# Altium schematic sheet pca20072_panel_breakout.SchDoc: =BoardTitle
size A4; Organization: Nordic Semiconductor; DocumentNumber: 4; SheetNumber: 4; SheetTotal: 6; CompanyName: Nordic Semiconductor; DocumentSize: A4
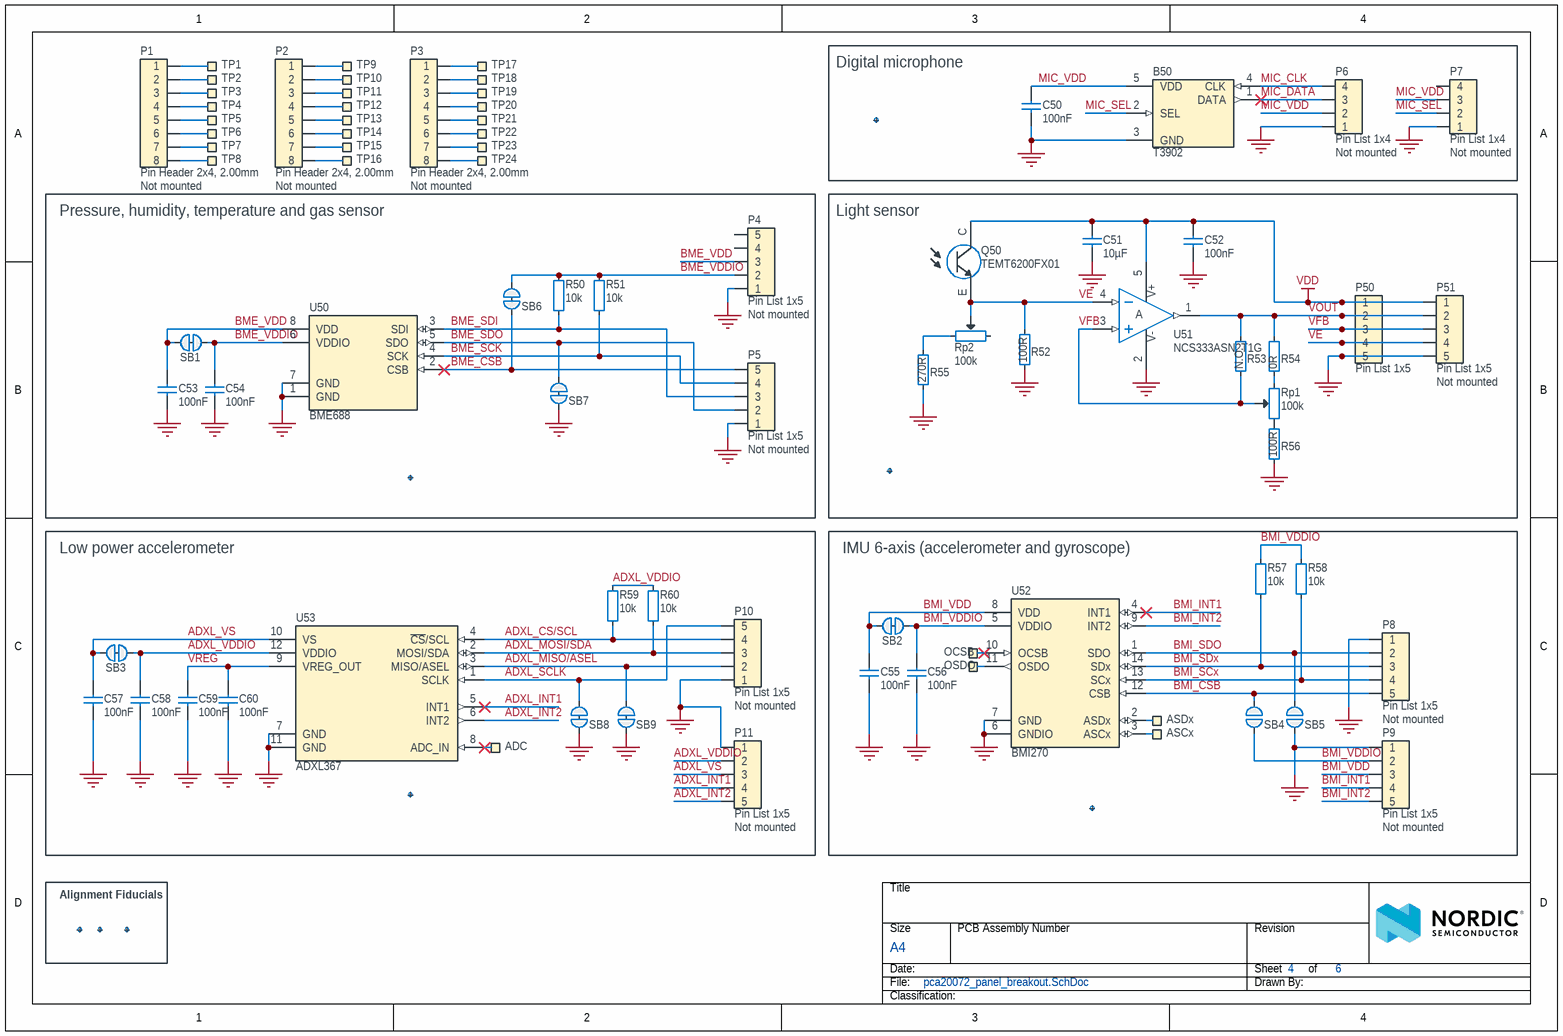
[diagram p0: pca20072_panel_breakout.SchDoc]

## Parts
ADC  Ø1.2mm,SMD  [TP_SMD_D1.2mm]  (value not drawn)  (no BOM)
ASCx  Ø1.2mm,SMD  [TP_SMD_D1.2mm]  (value not drawn)  (no BOM)
ASDx  Ø1.2mm,SMD  [TP_SMD_D1.2mm]  (value not drawn)  (no BOM)
B50  T3902  [T3902]
C50  100nF  [CAPC0603X03L_C]
C51  10µF  [CAPC1005X04L_C2]
C52  100nF  [CAPC0603X03L_C]
C53  100nF  [CAPC0603X03L_C]
C54  100nF  [CAPC0603X03L_C]
C55  100nF  [CAPC0603X03L_C]
C56  100nF  [CAPC0603X03L_C]
C57  100nF  [CAPC0603X03L_C]
C58  100nF  [CAPC0603X03L_C]
C59  100nF  [CAPC0603X03L_C]
C60  100nF  [CAPC0603X03L_C]
Fid50  Fiducial mark  [Fiducial]  (value not drawn)
Fid51  Fiducial mark  [Fiducial]  (value not drawn)
Fid52  Fiducial mark  [Fiducial]  (value not drawn)
Fid53  Fiducial mark  [Fiducial]  (value not drawn)
Fid54  Fiducial mark  [Fiducial]  (value not drawn)
Fid55  Fiducial mark  [Fiducial]  (value not drawn)
Fid56  Fiducial mark  [Fiducial]  (value not drawn)
Fid57  Fiducial mark  [Fiducial]  (value not drawn)
OCSB  Ø1.2mm,SMD  [TP_SMD_D1.2mm]  (value not drawn)  (no BOM)
OSDO  Ø1.2mm,SMD  [TP_SMD_D1.2mm]  (value not drawn)  (no BOM)
P1  Pin Header 2x4, 2.00mm  Assembly: Not mounted  [HDR_2x4_TH_2.00MM-NC]
P2  Pin Header 2x4, 2.00mm  Assembly: Not mounted  [HDR_2x4_TH_2.00MM-NC]
P3  Pin Header 2x4, 2.00mm  Assembly: Not mounted  [HDR_2x4_TH_2.00MM-NC]
P4  Pin List 1x5  Assembly: Not mounted  [LIST_1x5-NC]
P5  Pin List 1x5  Assembly: Not mounted  [LIST_1x5-NC]
P6  Pin List 1x4  Assembly: Not mounted  [LIST_1x4-NC]
P7  Pin List 1x4  Assembly: Not mounted  [LIST_1x4-NC]
P8  Pin List 1x5  Assembly: Not mounted  [LIST_1x5-NC]
P9  Pin List 1x5  Assembly: Not mounted  [LIST_1x5-NC]
P10  Pin List 1x5  Assembly: Not mounted  [LIST_1x5-NC]
P11  Pin List 1x5  Assembly: Not mounted  [LIST_1x5-NC]
P50  Pin List 1x5  [LIST_1x5_SMD]
P51  Pin List 1x5  Assembly: Not mounted  [LIST_1x5-NC]
Q50  TEMT6200FX01  [TEMT6200FX01]
R50  10k  [RESC1005X04L]
R51  10k  [RESC1005X04L]
R52  100R  [RESC1005X04L]
R53  N.C.  [RESC1005X04L_NC]
R54  0R  [RESC1005X04L]
R55  270R  [RESC1005X04L]
R56  100R  [RESC1005X04L]
R57  10k  [RESC1005X04L]
R58  10k  [RESC1005X04L]
R59  10k  [RESC1005X04L]
R60  10k  [RESC1005X04L]
Rp1  100k  [POT.TRIM_23B]
Rp2  100k  [POT.TRIM_23B]
SB1  Solderbridge  [Solderbridge_Shorted]  (value not drawn)  (net tie, no BOM)
SB2  Solderbridge  [Solderbridge_Shorted]  (value not drawn)  (net tie, no BOM)
SB3  Solderbridge  [Solderbridge_Shorted]  (value not drawn)  (net tie, no BOM)
SB4  Solderbridge  [Solderbridge]  (value not drawn)  (no BOM)
SB5  Solderbridge  [Solderbridge]  (value not drawn)  (no BOM)
SB6  Solderbridge  [Solderbridge_Shorted]  (value not drawn)  (net tie, no BOM)
SB7  Solderbridge  [Solderbridge_Shorted]  (value not drawn)  (net tie, no BOM)
SB8  Solderbridge  [Solderbridge_Shorted]  (value not drawn)  (net tie, no BOM)
SB9  Solderbridge  [Solderbridge_Shorted]  (value not drawn)  (net tie, no BOM)
TP1  TP  [TESTPAD-TH]  (value not drawn)  (no BOM)
TP2  TP  [TESTPAD-TH]  (value not drawn)  (no BOM)
TP3  TP  [TESTPAD-TH]  (value not drawn)  (no BOM)
TP4  TP  [TESTPAD-TH]  (value not drawn)  (no BOM)
TP5  TP  [TESTPAD-TH]  (value not drawn)  (no BOM)
TP6  TP  [TESTPAD-TH]  (value not drawn)  (no BOM)
TP7  TP  [TESTPAD-TH]  (value not drawn)  (no BOM)
TP8  TP  [TESTPAD-TH]  (value not drawn)  (no BOM)
TP9  TP  [TESTPAD-TH]  (value not drawn)  (no BOM)
TP10  TP  [TESTPAD-TH]  (value not drawn)  (no BOM)
TP11  TP  [TESTPAD-TH]  (value not drawn)  (no BOM)
TP12  TP  [TESTPAD-TH]  (value not drawn)  (no BOM)
TP13  TP  [TESTPAD-TH]  (value not drawn)  (no BOM)
TP14  TP  [TESTPAD-TH]  (value not drawn)  (no BOM)
TP15  TP  [TESTPAD-TH]  (value not drawn)  (no BOM)
TP16  TP  [TESTPAD-TH]  (value not drawn)  (no BOM)
TP17  TP  [TESTPAD-TH]  (value not drawn)  (no BOM)
TP18  TP  [TESTPAD-TH]  (value not drawn)  (no BOM)
TP19  TP  [TESTPAD-TH]  (value not drawn)  (no BOM)
TP20  TP  [TESTPAD-TH]  (value not drawn)  (no BOM)
TP21  TP  [TESTPAD-TH]  (value not drawn)  (no BOM)
TP22  TP  [TESTPAD-TH]  (value not drawn)  (no BOM)
TP23  TP  [TESTPAD-TH]  (value not drawn)  (no BOM)
TP24  TP  [TESTPAD-TH]  (value not drawn)  (no BOM)
U50  BME688  [BME680]
U51  NCS333ASN2T1G  [SOT95P275X110-5N]
U52  BMI270  [BMI270]
U53  ADXL367  [LGA50P220X230X97-12N]

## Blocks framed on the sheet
Digital microphone: B50 C50 Fid50 P6 P7
Pressure, humidity, temperature and gas sensor: C53 C54 Fid52 P4 P5 R50 R51 SB1 SB6 SB7 U50
Light sensor: C51 C52 Fid51 P50 P51 Q50 R52-R56 Rp1 Rp2 U51
Low power accelerometer: ADC C57-C60 Fid54 P10 P11 R59 R60 SB3 SB8 SB9 U53
IMU 6-axis (accelerometer and gyroscope): ASCx ASDx C55 C56 Fid53 OCSB OSDO P8 P9 R57 R58 SB2 SB4 SB5 U52
Alignment Fiducials: Fid55-Fid57

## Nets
GND: B50.3(GND) C50.1 C51.2 C52.2 C53.1 C54.1 C55.1 C56.1 C57.1 C58.1 C59.1 C60.1 P4.1 P5.1 P6.1 P7.1 P8.1 P9.1 P10.1 P11.1 P50.5 P51.5 R52.1 R55.1 R56.1 SB5.2 SB7.2 SB8.2 SB9.2 U50.1(GND) U50.7(GND) U51.2(VSS) U52.6(GNDIO) U52.7(GND) U53.7(GND) U53.11(GND)
VDD: C51.1 C52.1 P50.1 P51.1 Q50.C U51.5(VDD)
ADXL_CS/SCL: P10.4 R59.2 U53.4(~{CS}/SCL)
ADXL_INT1: P11.4 U53.5(INT1)
ADXL_INT2: P11.5 U53.6(INT2)
ADXL_MISO/ASEL: P10.2 SB9.1 U53.3(MISO/ASEL)
ADXL_MOSI/SDA: P10.3 R60.2 U53.2(MOSI/SDA)
ADXL_SCLK: P10.5 SB8.1 U53.1(SCLK)
ADXL_VDDIO: C58.2 P11.2 R59.1 R60.1 SB3.2 U53.12(VDDIO)
ADXL_VS: C57.2 P11.3 SB3.1 U53.10(VS)
BME_CSB: P5.5 SB6.1 U50.2(CSB)
BME_SCK: P5.4 R51.2 U50.4(SCK)
BME_SDI: P5.3 R50.2 U50.3(SDI)
BME_SDO: P5.2 SB7.1 U50.5(SDO)
BME_VDD: C53.2 P4.3 SB1.2 U50.8(VDD)
BME_VDDIO: C54.2 P4.2 R50.1 R51.1 SB1.1 SB6.2 U50.6(VDDIO)
BMI_CSB: P8.5 SB4.1 U52.12(CSB)
BMI_INT1: P9.4 U52.4(INT1)
BMI_INT2: P9.5 U52.9(INT2)
BMI_SCx: P8.4 R58.2 U52.13(SCx)
BMI_SDO: P8.2 SB5.1 U52.1(SDO)
BMI_SDx: P8.3 R57.2 U52.14(SDx)
BMI_VDD: C55.2 P9.3 SB2.1 U52.8(VDD)
BMI_VDDIO: C56.2 P9.2 R57.1 R58.1 SB2.2 SB4.2 U52.5(VDDIO)
MIC_CLK: B50.4(CLK) P6.4
MIC_DATA: B50.1(DATA) P6.3
MIC_SEL: B50.2(SEL) P7.2
MIC_VDD: B50.5(VDD) C50.2 P6.2 P7.3
VE: P50.4 P51.4 Q50.E R52.2 Rp2.3 U51.4(IN-)
VFB: P50.3 P51.3 R53.1 Rp1.3 U51.3(IN+)
VOUT: P50.2 P51.2 R53.2 R54.2 U51.1(OUT)
VREG: C59.2 C60.2 U53.9(VREG_OUT)
NetADC_1: ADC.1 U53.8(ADC_IN)
NetASCx_1: ASCx.1 U52.3(ASCx)
NetASDx_1: ASDx.1 U52.2(ASDx)
NetOCSB_1: OCSB.1 U52.10(OCSB)
NetOSDO_1: OSDO.1 U52.11(OSDO)
NetP1_1: P1.1 TP1.1
NetP1_2: P1.2 TP2.1
NetP1_3: P1.3 TP3.1
NetP1_4: P1.4 TP4.1
NetP1_5: P1.5 TP5.1
NetP1_6: P1.6 TP6.1
NetP1_7: P1.7 TP7.1
NetP1_8: P1.8 TP8.1
NetP2_1: P2.1 TP9.1
NetP2_2: P2.2 TP10.1
NetP2_3: P2.3 TP11.1
NetP2_4: P2.4 TP12.1
NetP2_5: P2.5 TP13.1
NetP2_6: P2.6 TP14.1
NetP2_7: P2.7 TP15.1
NetP2_8: P2.8 TP16.1
NetP3_1: P3.1 TP17.1
NetP3_2: P3.2 TP18.1
NetP3_3: P3.3 TP19.1
NetP3_4: P3.4 TP20.1
NetP3_5: P3.5 TP21.1
NetP3_6: P3.6 TP22.1
NetP3_7: P3.7 TP23.1
NetP3_8: P3.8 TP24.1
NetR54_1: R54.1 Rp1.1
NetR55_2: R55.2 Rp2.2
NetR56_2: R56.2 Rp1.2

Not connected (* = marked no-connect by the designer): P4 4 5; P7 4; Rp2 1

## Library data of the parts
ADC ASCx ASDx OCSB OSDO = TP_SMD_Ø1.2MM: 1.2mm circular SMD testpad; Manufacturer: Nordic Semiconductor; Manufacturer Part Number: N.A.; Part number NEMS: 100500476; Component Status: Active; Pad Count: 1
B50 = MMICT3902‐00‐012: Bottom Port PDM Low‐Power Multi‐Mode Microphone With High AOP Mode; Manufacturer: TDK Corporation; Part number NEMS: 101900855; Component Status: Active; Pad Count: 5; Note: N.A.
C50 C53 C54 C57-C60 = C0201-100n: Capacitor, X5R, ±10%, 100nF, 16V; Manufacturer: N.A.; Part number IPS: 00000001248, 00000002505; Part number Norautron: 262071862; Part number NEMS: 100200078; Component Status: Active; Pad Count: 2
C51 = C0402-10µ-6.3V-X5R-GRM155R60J106ME05D: Capacitor, X5R, ±20%, 6.3V; Manufacturer: Murata; Part number NEMS: 100200554; Pad Count: 2; Artikkelnr Noca: N.A.; Component Status: Active
C52 C55 C56 = C0201-100n: Capacitor, X5R, ±10%, 100nF, 16V; Manufacturer: N.A.; Part number IPS: 00000001248, 00000002505; Part number Norautron: 262071862; Part number NEMS: 100200078; Pad Count: 2; Component Status: Active
Fid50-Fid57 = Fid-Mark: Manufacturer: N.A.; Part number NEMS: 100500073; Value: N.A.; Pad Count: 1; Component Status: Active; System: Connector
P1-P3 = Pin Header 2x4 TH, 2.00mm, N.C.: Pin Header 2x4, TH, 2.00mm; Manufacturer: N.A.; Part number NEMS: 100500252; Component Status: Active; Pad Count: 6; System: Connector
P4 P5 P8-P11 P51 = Pin List 1x5, N.C.: Pin List 1x5, 2.54mm (100mil); Manufacturer: N.A.; Part number NEMS: 100500315; Component Status: Active; Pad Count: 5; System: Connector
P6 P7 = Pin List 1x4, N.C.: Pin List 1x4, 2.54mm (100mil); Manufacturer: N.A.; Part number NEMS: 100500310; Component Status: Active; Pad Count: 4; System: Connector
P50 = Pin List 1x5 SMD: Pin List 1x5, 2.54mm (100mil), SMD; Manufacturer: WCON; Manufacturer Part Number: 1125-1105S0M116R1; Part number NEMS: 100500316; Component Status: Active; Pad Count: 5; Note: N.A.; System: Connector
Q50 = TEMT6200FX01: Phototransistors 550nm Top View 0805 (2012 Metric); Manufacturer: Vishay Semiconductor Opto Division; Part number NEMS: 101400145; Component Status: Active; Pad Count: 2; Note: N.A.
R50 R51 R57-R60 = R0402-10k: Resistor, ±1%, 0.063W; Manufacturer: N.A.; Part number IPS: 00000002093; Part number NEMS: 100100198; Component Status: Active; Pad Count: 2; Note: Chip Res 1%; Artikkelnr Noca: 27049097
R52 R56 = R0402-100: Resistor, ±1%, 0.063W; Manufacturer: N.A.; Part number IPS: 00000002811; Part number NEMS: 100100148; Component Status: Active; Pad Count: 2; Note: Chip Res 1%; Artikkelnr Noca: 27049049
R53 = R0402-N.C.: Not mounted; Manufacturer: N.A.; Part number NEMS: 100100281; Component Status: Active; Pad Count: 2; Note: Chip Res; Assembly: Not mounted
R54 = R0402-0R: Resistor, ±5%, 0.063W; Manufacturer: N.A.; Part number IPS: 00000007128; Part number NEMS: 100100109; Component Status: Active; Pad Count: 2; Note: Chip Res 5%; Artikkelnr Noca: 27049000
R55 = R0402-270: Resistor, ±1%, 0.063W; Manufacturer: N.A.; Part number NEMS: 100100158; Component Status: Active; Pad Count: 2; Note: Chip Res 1%; Artikkelnr Noca: 27049059
Rp1 Rp2 = Trimpot_23B_100k: BI techolygies, CB10V Series trim.pot; Manufacturer: N.A.; Part number NEMS: 100100516; Component Status: Active; Pad Count: 3
SB1-SB3 SB6-SB9 = Solderbridge Shorted: Shorted Solderbridge; Manufacturer: N.A.; Part number NEMS: 100500459; Component Status: Active; Pad Count: 2; System: Connector
SB4 SB5 = Solderbridge: Manufacturer: N.A.; Part number NEMS: 100500458; Component Status: Active; Pad Count: 2; System: Connector
TP1-TP24 = Testpoint TH: Testpoint, through hole; Manufacturer: N.A.; Part number NEMS: 100500464; Component Status: Active; Pad Count: 1
U50 = BME688: Low power gas, pressure, temperature & humidity sensor; Manufacturer: Bosch; Part number NEMS: 101900619; Component Status: Active; Pad Count: 8; Note: N.A.
U51 = NCS333ASN2T1G: Low Power, Zero-Drift Operational Amplifier; Manufacturer: Onsemi; Part number NEMS: 101900755; Pad Count: 5; Note: N.A.; Component Status: Active
U52 = BMI270: 6-axis, smart, low-power, inertial measurement unit; Manufacturer: Bosch; Part number NEMS: 101900620; Note: N.A.; Pad Count: 14; Component Status: Active
U53 = ADXL367BCCZ: Micropower, 3-Axis, ±2 g/±4 g/±8 g Digital Output MEMS Accelerometer; Manufacturer: Analog Devices; Part number NEMS: 101900775; Note: N.A.; Component Status: Active; Pad Count: 12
